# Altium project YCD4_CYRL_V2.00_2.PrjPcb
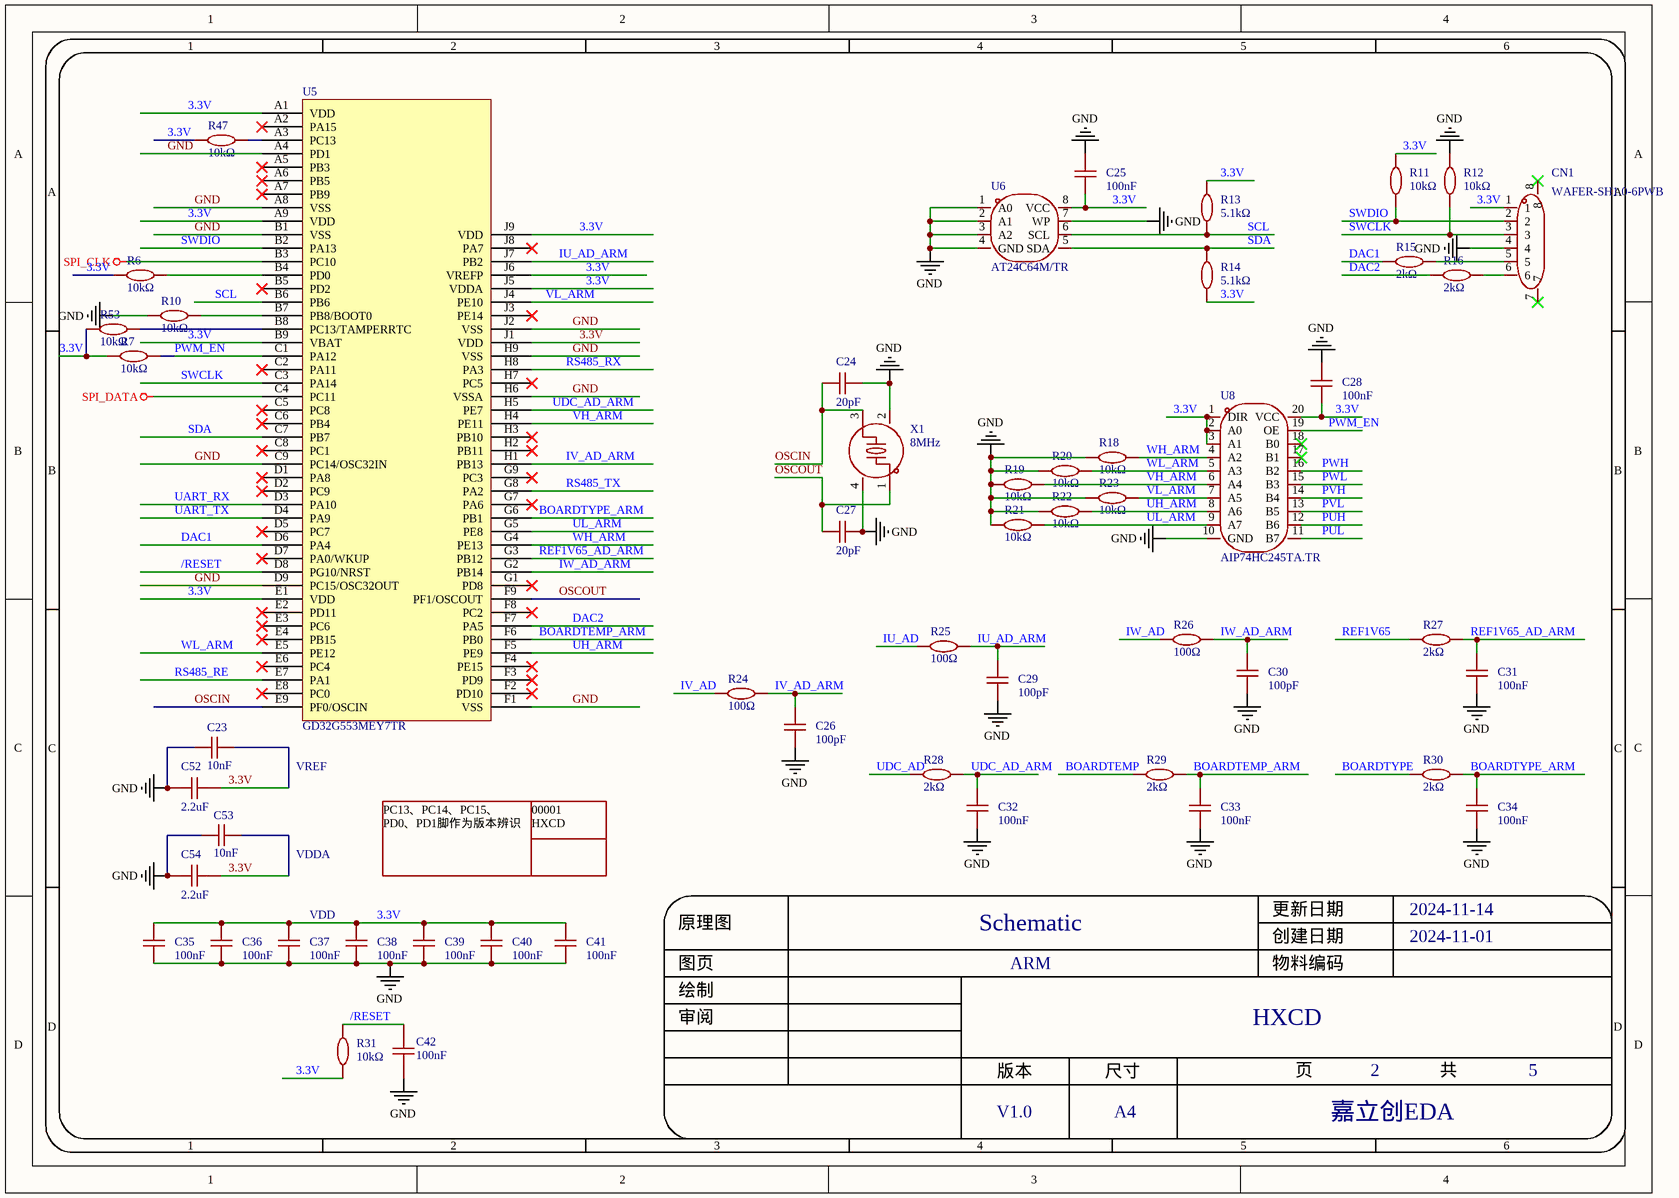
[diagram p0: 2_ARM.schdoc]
5 sheets, 208 parts. Net scope: global (net labels, ports and power ports of the same name join across sheets).
Board file: YCD4_CYRL_V2.00_2.PcbDoc
Sheets:
  2_ARM.schdoc
  5_DRIVE.schdoc
  3_COM.schdoc
  4_SAMP.schdoc
  1_POWER.schdoc

## Sheet 2_ARM.schdoc
size 309 x 223 mm; Symbol: Sheet-Symbol_A4; Device: Sheet-Symbol_A4; Company: 嘉立创EDA; Version: V1.0; Page Size: A4; @Project Name: HXCD; @Page Count: 5; @Update Date: 2024-11-14; @Create Date: 2024-11-01; @Schematic Name: Schematic; @Page No: 2; @Page Name: ARM; @Board Name: Board1; @Create Time: 20:30:37; @Update Time: 22:14:38; SheetNumber: 1; SheetTotal: 5

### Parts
C23  10nF  [C0402]
C24  20pF  [C0402]
C25  100nF  [C0402]
C26  100pF  [C0402]
C27  20pF  [C0402]
C28  100nF  [C0402]
C29  100pF  [C0402]
C30  100pF  [C0402]
C31  100nF  [C0402]
C32  100nF  [C0402]
C33  100nF  [C0402]
C34  100nF  [C0402]
C35  100nF  [C0402]
C36  100nF  [C0402]
C37  100nF  [C0402]
C38  100nF  [C0402]
C39  100nF  [C0402]
C40  100nF  [C0402]
C41  100nF  [C0402]
C42  100nF  [C0402]
C52  2.2uF  [C0402]
C53  10nF  [C0402]
C54  2.2uF  [C0402]
CN1  WAFER-SH1.0-6PWB  [CONN-SMD_6P-P1.00_XUNPU_WAFER-SH1.0-6PWB]
R6  10kΩ  [R0402]
R7  10kΩ  [R0402]
R10  10kΩ  [R0402]
R11  10kΩ  [R0402]
R12  10kΩ  [R0402]
R13  5.1kΩ  [R0402]
R14  5.1kΩ  [R0402]
R15  2kΩ  [R0402]
R16  2kΩ  [R0402]
R18  10kΩ  [R0402]
R19  10kΩ  [R0402]
R20  10kΩ  [R0402]
R21  10kΩ  [R0402]
R22  10kΩ  [R0402]
R23  10kΩ  [R0402]
R24  100Ω  [R0402]
R25  100Ω  [R0402]
R26  100Ω  [R0402]
R27  2kΩ  [R0402]
R28  2kΩ  [R0402]
R29  2kΩ  [R0402]
R30  2kΩ  [R0402]
R31  10kΩ  [R0402]
R47  10kΩ  [R0402]
R53  10kΩ  [R0402]
U5  GD32G553MEY7TR  [GD32G553MEY7TR]
U6  AT24C64M/TR  [SOP-8_L4.9-W3.9-P1.27-LS6.0-BL]
U8  AIP74HC245TA.TR  [TSSOP-20_L6.5-W4.4-P0.65-LS6.4-BL]
X1  8MHz  [CRYSTAL-SMD_4P-L3.2-W2.5-BL]

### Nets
3.3V: C23.2 C25.2 C28.2 C35.1 C36.1 C37.1 C38.1 C39.1 C40.1 C41.1 C52.1 C53.2 C54.1 CN1.1 R6.2 R7.2 R11.1 R13.2 R14.1 R31.2 R47.2 R53.2 U5.A1(VDD) U5.A9(VDD) U5.B9(VBAT) U5.E1(VDD) U5.J1(VDD) U5.J5(VDDA) U5.J6(VREFP) U5.J9(VDD) U6.8(VCC) U8.1(DIR) U8.2(A0) U8.3(A1) U8.20(VCC)
GND: C23.1 C24.2 C25.1 C26.1 C27.2 C28.1 C29.1 C30.1 C31.2 C32.2 C33.2 C34.2 C35.2 C36.2 C37.2 C38.2 C39.2 C40.2 C41.2 C42.1 C52.2 C53.1 C54.2 CN1.4 R10.2 R12.1 R18.2 R19.2 R20.2 R21.2 R22.2 R23.2 U5.A4(PD1) U5.A8(VSS) U5.B1(VSS) U5.C9(PC14/OSC32IN) U5.D9(PC15/OSC32OUT) U5.F1(VSS) U5.H6(VSSA) U5.H9(VSS) U5.J2(VSS) U6.1(A0) U6.2(A1) U6.3(A2) U6.4(GND) U6.7(WP) U8.10(GND) X1.2(GND) X1.4(GND)
SPI_CLK: U5.B3(PC10)
SPI_DATA: U5.C4(PC11)
/RESET: C42.2 R31.1 U5.D8(PG10/NRST)
BOARDTEMP: R29.1
BOARDTEMP_ARM: C33.1 R29.2 U5.F6(PB0)
BOARDTYPE: R30.1
BOARDTYPE_ARM: C34.1 R30.2 U5.G6(PB1)
DAC1: R15.1 U5.D6(PA4)
DAC2: R16.1 U5.F7(PA5)
IU_AD: R25.1
IU_AD_ARM: C29.2 R25.2 U5.J7(PB2)
IV_AD: R24.1
IV_AD_ARM: C26.2 R24.2 U5.H1(PB13)
IW_AD: R26.1
IW_AD_ARM: C30.2 R26.2 U5.G2(PB14)
OSCIN: C24.1 U5.E9(PF0/OSCIN) X1.3
OSCOUT: C27.1 U5.F9(PF1/OSCOUT) X1.1
PUH: U8.12(B6)
PUL: U8.11(B7)
PVH: U8.14(B4)
PVL: U8.13(B5)
PWH: U8.16(B2)
PWL: U8.15(B3)
PWM_EN: R7.1 U5.C1(PA12) U8.19(OE)
REF1V65: R27.1
REF1V65_AD_ARM: C31.1 R27.2 U5.G3(PB12)
RS485_RE: U5.E7(PA1)
RS485_RX: U5.H8(PA3)
RS485_TX: U5.G8(PA2)
SCL: R13.1 U5.B6(PB6) U6.6(SCL)
SDA: R14.2 U5.C7(PB7) U6.5(SDA)
SWCLK: CN1.3 R12.2 U5.C3(PA14)
SWDIO: CN1.2 R11.2 U5.B2(PA13)
UART_RX: U5.D3(PA10)
UART_TX: U5.D4(PA9)
UDC_AD: R28.1
UDC_AD_ARM: C32.1 R28.2 U5.H5(PE7)
UH_ARM: R22.1 U5.F5(PE9) U8.8(A6)
UL_ARM: R21.1 U5.G5(PE8) U8.9(A7)
VH_ARM: R19.1 U5.H4(PE11) U8.6(A4)
VL_ARM: R23.1 U5.J4(PE10) U8.7(A5)
WH_ARM: R18.1 U5.G4(PE13) U8.4(A2)
WL_ARM: R20.1 U5.E5(PE12) U8.5(A3)
NetCN1_5: CN1.5 R15.2
NetCN1_6: CN1.6 R16.2
NetR6_1: R6.1 U5.B4(PD0)
NetR10_1: R10.1 U5.B7(PB8/BOOT0)
NetR47_1: R47.1 U5.A3(PC13)
NetR53_1: R53.1 U5.B8(PC13/TAMPERRTC)

Not connected (* = marked no-connect by the designer): CN1 7* 8*; U5 A2(PA15)* A5(PB3)* A6(PB5)* A7(PB9)* B5(PD2)* C2(PA11)* C5(PC8)* C6(PB4)* C8(PC1)* D1(PA8)* D2(PC9)* D5(PC7)* D7(PA0/WKUP)* E2(PD11)* E3(PC6)* E4(PB15)* E6(PC4)* E8(PC0)* F2(PD10)* F3(PD9)* F4(PE15)* F8(PC2)* G1(PD8)* G7(PA6)* G9(PC3)* H2(PB11)* H3(PB10)* H7(PC5)* J3(PE14)* J8(PA7)*; U8 17(B1)* 18(B0)*

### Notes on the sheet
- VREF
- VDDA
- PC13、PC14、PC15、
  PD0、PD1脚作为版本辨识
- 00001
  HXCD
- VDD

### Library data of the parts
C23 C53 = CC0402KRX7R9BB104: 容值:100nF;精度:±10%;额定电压:50V;材质(温度系数):X7R;; Manufacturer: YAGEO(国巨); Add into BOM: yes; Value: 100nF; Tolerance: ±10%; Voltage Rated: 50V; Temperature Coefficient: X7R
C24 C27 = 0402CG200J500NT: 容值:20pF;精度:±5%;额定电压:50V;材质(温度系数):C0G;; Manufacturer: FH(风华); Add into BOM: yes; Tolerance: ±5%; Voltage Rated: 50V; Temperature Coefficient: C0G
C25 C28 C31-C41 = CC0402KRX7R9BB104: 容值:100nF;精度:±10%;额定电压:50V;材质(温度系数):X7R;; Manufacturer: YAGEO(国巨); Add into BOM: yes; Tolerance: ±10%; Voltage Rated: 50V; Temperature Coefficient: X7R
C26 C29 C30 = 0402CG101J500NT: 容值:100pF;精度:±5%;额定电压:50V;材质(温度系数):C0G;; Manufacturer: FH(风华); Add into BOM: yes; Tolerance: ±5%; Voltage Rated: 50V; Temperature Coefficient: C0G
C42 = CC0402KRX7R9BB104: 容值:100nF;精度:±10%;额定电压:50V;材质(温度系数):X7R;; Manufacturer: YAGEO(国巨); Symbol: CC0603KRX7R0BB104; Add into BOM: yes; Tolerance: ±10%; Voltage Rated: 50V; Temperature Coefficient: X7R
C52 C54 = CC0402KRX5R6BB225: 容值:2.2uF;精度:±10%;额定电压:10V;材质(温度系数):X5R;; Manufacturer: YAGEO(国巨); Add into BOM: yes; Tolerance: ±10%; Voltage Rated: 10V; Temperature Coefficient: X5R
CN1 = WAFER-SH1.0-6PWB: 插针结构:1x6P;间距:1mm;安装方式:卧贴;总PIN数:6P;排数:1;每排PIN数:6;额定电流:1A;工作温度范围:-25℃~+85℃;; Manufacturer: XUNPU(讯普); Add into BOM: yes; Pins Structure: 1x6P; Pitch: 1mm; Number of PINs Per Row: 6; Current Rating (Max): 1A
R6 R7 R10-R12 R31 R47 R53 = 0402WGF1002TCE: 电阻类型:厚膜电阻;阻值:10kΩ;精度:±1%;功率:62.5mW;最大工作电压:50V;温度系数:±100ppm/℃;; Manufacturer: UNI-ROYAL(厚声); Add into BOM: yes; Tolerance: ±1%; Power(Watts): 62.5mW; Overload Voltage (Max): 50V
R13 R14 = 0402WGF5101TCE: 电阻类型:厚膜电阻;阻值:5.1kΩ;精度:±1%;功率:62.5mW;最大工作电压:50V;温度系数:±100ppm/℃;; Manufacturer: UNI-ROYAL(厚声); Symbol: 0603WAF5101T5E; Add into BOM: yes; Tolerance: ±1%; Power(Watts): 62.5mW; Overload Voltage (Max): 50V
R15 R16 R27-R30 = 0402WGF2001TCE: 电阻类型:厚膜电阻;阻值:2kΩ;精度:±1%;功率:62.5mW;最大工作电压:50V;温度系数:±100ppm/℃;; Manufacturer: UNI-ROYAL(厚声); Symbol: 0603WAF2001T5E; Add into BOM: yes; Tolerance: ±1%; Power(Watts): 62.5mW; Overload Voltage (Max): 50V
R18-R23 = 0402WGF1002TCE: 电阻类型:厚膜电阻;阻值:10kΩ;精度:±1%;功率:62.5mW;最大工作电压:50V;温度系数:±100ppm/℃;; Manufacturer: UNI-ROYAL(厚声); Symbol: RT0603BRE0710KL; Add into BOM: yes; Tolerance: ±1%; Power(Watts): 62.5mW; Overload Voltage (Max): 50V
R24-R26 = 0402WGF2001TCE: 电阻类型:厚膜电阻;阻值:2kΩ;精度:±1%;功率:62.5mW;最大工作电压:50V;温度系数:±100ppm/℃;; Manufacturer: UNI-ROYAL(厚声); Symbol: 0603WAF2001T5E; Add into BOM: yes; Value: 2kΩ; Tolerance: ±1%; Power(Watts): 62.5mW; Overload Voltage (Max): 50V
U6 = AT24C64M/TR: Manufacturer: HGSEMI(华冠); Add into BOM: yes
U8 = AIP74HC245TA.TR: 输入类型:-;电源电压:2V~6V;灌电流(IOL):7.8mA;拉电流(IOH):7.8mA;; Manufacturer: I-CORE(中微爱芯); Add into BOM: yes; output type: 三态; Supply Voltage: 2V~6V; Sink Current: 7.8mA
X1 = X32258MSB4SI: 晶振类型:贴片晶振;频率:8MHz;常温频差:±10ppm;外接负载电容:20pF;频率稳定度(全温):±20ppm;; Manufacturer: YXC(扬兴晶振); Add into BOM: yes; Crystal Type: 贴片晶振; Normal temperature Frequency Tolerance: ±10ppm; External load capacitor: 20pF; Frequency Stability(Full temperature range): ±20ppm

## Sheet 5_DRIVE.schdoc
size 309 x 223 mm; Symbol: Sheet-Symbol_A4; Device: Sheet-Symbol_A4; Company: 嘉立创EDA; Version: V1.0; Page Size: A4; @Project Name: HXCD; @Page Count: 5; @Update Date: 2024-11-15; @Create Date: 2024-11-06; @Schematic Name: Schematic; @Page No: 5; @Page Name: DRIVE; @Board Name: Board1; @Create Time: 09:37:48; @Update Time: 20:32:39; SheetNumber: 2; SheetTotal: 5
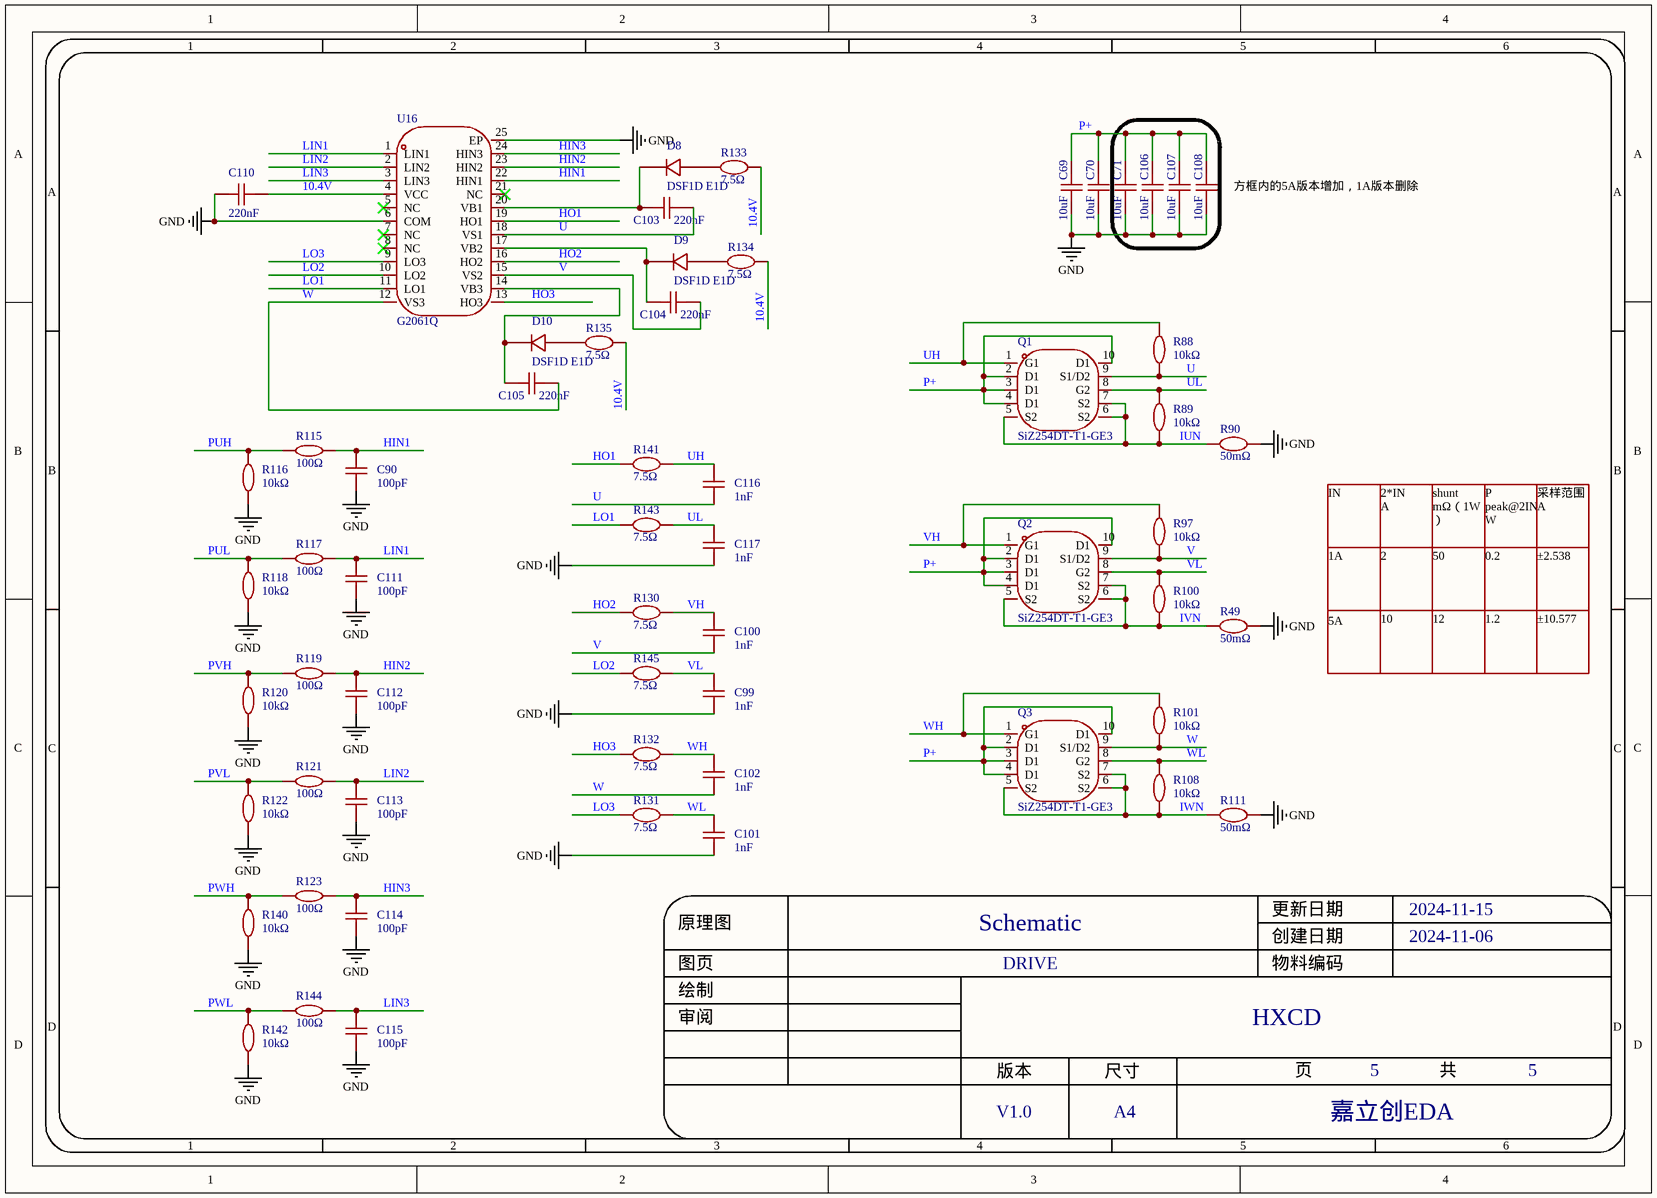
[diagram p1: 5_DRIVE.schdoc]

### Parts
C69  10uF  [C1210]
C70  10uF  [C1210]
C71  10uF  [C1210]
C90  100pF  [C0402]
C99  1nF  [C0402]
C100  1nF  [C0402]
C101  1nF  [C0402]
C102  1nF  [C0402]
C103  220nF  [C0402]
C104  220nF  [C0402]
C105  220nF  [C0402]
C106  10uF  [C1210]
C107  10uF  [C1210]
C108  10uF  [C1210]
C110  220nF  [C0402]
C111  100pF  [C0402]
C112  100pF  [C0402]
C113  100pF  [C0402]
C114  100pF  [C0402]
C115  100pF  [C0402]
C116  1nF  [C0402]
C117  1nF  [C0402]
D8  DSF1D E1D  [SOD-123_L2.8-W1.8-LS3.7-RD]
D9  DSF1D E1D  [SOD-123_L2.8-W1.8-LS3.7-RD]
D10  DSF1D E1D  [SOD-123_L2.8-W1.8-LS3.7-RD]
Q1  SiZ254DT-T1-GE3  [POWERPAIR-8_L3.3-W3.3-P0.65-BL_SIZ260DT-T1-GE3]
Q2  SiZ254DT-T1-GE3  [POWERPAIR-8_L3.3-W3.3-P0.65-BL_SIZ260DT-T1-GE3]
Q3  SiZ254DT-T1-GE3  [POWERPAIR-8_L3.3-W3.3-P0.65-BL_SIZ260DT-T1-GE3]
R49  50mΩ  [1206R]
R88  10kΩ  [R0402]
R89  10kΩ  [R0402]
R90  50mΩ  [R1206]
R97  10kΩ  [R0402]
R100  10kΩ  [R0402]
R101  10kΩ  [R0402]
R108  10kΩ  [R0402]
R111  50mΩ  [R1206]
R115  100Ω  [R0402]
R116  10kΩ  [R0402]
R117  100Ω  [R0402]
R118  10kΩ  [R0402]
R119  100Ω  [R0402]
R120  10kΩ  [R0402]
R121  100Ω  [R0402]
R122  10kΩ  [R0402]
R123  100Ω  [R0402]
R130  7.5Ω  [R0603]
R131  7.5Ω  [R0603]
R132  7.5Ω  [R0603]
R133  7.5Ω  [R0603]
R134  7.5Ω  [R0603]
R135  7.5Ω  [R0603]
R140  10kΩ  [R0402]
R141  7.5Ω  [R0603]
R142  10kΩ  [R0402]
R143  7.5Ω  [R0603]
R144  100Ω  [R0402]
R145  7.5Ω  [R0603]
U16  G2061Q  [QFN-24_L4.0-W4.0-P0.50-TL-EP2.7]

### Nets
10.4V: C110.2 R133.2 R134.2 R135.2 U16.4(VCC)
GND: C69.2 C70.2 C71.2 C90.1 C99.1 C101.1 C106.2 C107.2 C108.2 C110.1 C111.1 C112.1 C113.1 C114.1 C115.1 C117.1 R49.1 R90.1 R111.1 R116.1 R118.1 R120.1 R122.1 R140.1 R142.1 U16.6(COM) U16.25(EP)
HIN1: C90.2 R115.2 U16.22(HIN1)
HIN2: C112.2 R119.2 U16.23(HIN2)
HIN3: C114.2 R123.2 U16.24(HIN3)
HO1: R141.1 U16.19(HO1)
HO2: R130.1 U16.16(HO2)
HO3: R132.1 U16.13(HO3)
IUN: Q1.5(S2) Q1.6(S2) Q1.7(S2) R89.1 R90.2
IVN: Q2.5(S2) Q2.6(S2) Q2.7(S2) R49.2 R100.1
IWN: Q3.5(S2) Q3.6(S2) Q3.7(S2) R108.1 R111.2
LIN1: C111.2 R117.2 U16.1(LIN1)
LIN2: C113.2 R121.2 U16.2(LIN2)
LIN3: C115.2 R144.2 U16.3(LIN3)
LO1: R143.1 U16.11(LO1)
LO2: R145.1 U16.10(LO2)
LO3: R131.1 U16.9(LO3)
P+: C69.1 C70.1 C71.1 C106.1 C107.1 C108.1 Q1.2(D1) Q1.3(D1) Q1.4(D1) Q1.10(D1) Q2.2(D1) Q2.3(D1) Q2.4(D1) Q2.10(D1) Q3.2(D1) Q3.3(D1) Q3.4(D1) Q3.10(D1)
PUH: R115.1 R116.2
PUL: R117.1 R118.2
PVH: R119.1 R120.2
PVL: R121.1 R122.2
PWH: R123.1 R140.2
PWL: R142.2 R144.1
U: C103.1 C116.1 Q1.9(S1/D2) R88.1 U16.18(VS1)
UH: C116.2 Q1.1(G1) R88.2 R141.2
UL: C117.2 Q1.8(G2) R89.2 R143.2
V: C100.1 C104.1 Q2.9(S1/D2) R97.1 U16.15(VS2)
VH: C100.2 Q2.1(G1) R97.2 R130.2
VL: C99.2 Q2.8(G2) R100.2 R145.2
W: C102.1 C105.1 Q3.9(S1/D2) R101.1 U16.12(VS3)
WH: C102.2 Q3.1(G1) R101.2 R132.2
WL: C101.2 Q3.8(G2) R108.2 R131.2
NetC103_2: C103.2 D8.1 U16.20(VB1)
NetC104_2: C104.2 D9.1 U16.17(VB2)
NetC105_2: C105.2 D10.1 U16.14(VB3)
NetD8_2: D8.2 R133.1
NetD9_2: D9.2 R134.1
NetD10_2: D10.2 R135.1

Not connected (* = marked no-connect by the designer): U16 5(NC)* 7(NC)* 8(NC)* 21(NC)*

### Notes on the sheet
- (near C108) 方框内的5A版本增加，1A版本删除
- IN
- 1A
- 2*IN
  A
- 2
- shunt
  mΩ（1W）
- 50
- P peak@2IN
  W
- 0.2
- 采样范围
  A
- ±2.538
- 5A
- 10
- 12
- 1.2
- ±10.577

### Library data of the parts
C69 C70 = C1210X7R106K101NT: 容值:10uF;额定电压:100V;温度系数:-;; Manufacturer: SANYEAR(叁叶源); Add into BOM: yes; Voltage Rated: 100V
C71 C106-C108 = C1210X7R106K101NT: 容值:10uF;额定电压:100V;温度系数:-;; Manufacturer: SANYEAR(叁叶源); Add into BOM: no; Voltage Rated: 100V
C90 C111-C115 = 0402CG101J500NT: as C26 on sheet 2_ARM
C99-C102 C116 C117 = CC0402KRX7R9BB102: 容值:1nF;精度:±10%;额定电压:50V;材质(温度系数):X7R;; Manufacturer: YAGEO(国巨); Add into BOM: yes; Tolerance: ±10%; Voltage Rated: 50V; Temperature Coefficient: X7R
C103-C105 C110 = GRM155R61H224KE01D: 容值:220nF;精度:±10%;额定电压:50V;材质(温度系数):X5R;; Manufacturer: muRata(村田); Add into BOM: yes; Tolerance: ±10%; Voltage Rated: 50V; Temperature Coefficient: X5R
D8-D10 = DSF1D E1D: 二极管配置:独立式;正向压降(Vf):1V@1A;直流反向耐压(Vr):200V;整流电流:1A;反向恢复时间(trr):35ns;; Manufacturer: MDD(辰达半导体); Add into BOM: yes; Diode Configuration: 独立式; Forward Voltage (Vf@If): 1V@1A; Reverse Voltage (Vr): 200V; Rectified Current: 1A; Reverse Leakage Current: 5uA@200V; Reverse Recovery Time (trr): 35ns
Q1-Q3 = SiZ254DT-T1-GE3: Manufacturer: VISHAY(威世); Add into BOM: yes
R49 R90 R111 = RLM12FTCMR050: 电阻类型:采样电阻;阻值:50mΩ;精度:±1%;额定压降:-;功率:1W;安装方式:贴片;; Manufacturer: 大毅科技; Add into BOM: yes; Tolerance: ±1%; Power(Watts): 1W; Mounting Sytle: 贴片
R88 R89 R97 R100 R101 R108 R116 R118 R120 R122 R140 R142 = 0402WGF1002TCE: as R6 on sheet 2_ARM
R115 R117 R119 R121 R123 R144 = 0402WGF1000TCE: 电阻类型:厚膜电阻;阻值:100Ω;精度:±1%;功率:62.5mW;最大工作电压:50V;温度系数:±200ppm/℃;; Manufacturer: UNI-ROYAL(厚声); Add into BOM: yes; Tolerance: ±1%; Power(Watts): 62.5mW; Overload Voltage (Max): 50V
R130-R135 R141 R143 R145 = FRC0603F7R50TS: 电阻类型:厚膜电阻;阻值:7.5Ω;精度:±1%;功率:100mW;最大工作电压:75V;温度系数:±200ppm/℃;; Manufacturer: FOJAN(富捷); Add into BOM: yes; Tolerance: ±1%; Power(Watts): 100mW; Overload Voltage (Max): 75V
U16 = G2061Q: 驱动通道数:6;峰值灌电流:1.8A;峰值拉电流:1.5A;电源电压:8V~20V;上升时间:30ns;下降时间:30ns;是否隔离:非隔离;; Manufacturer: WXNSIC(国硅集成); Add into BOM: yes; Number of Drivers: 6; Peak Output Current(sink): 1.8A; Peak Output Current(source): 1.5A; Supply Voltage: 8V~20V; Rise Time: 30ns; Whether the isolation: 非隔离

## Sheet 3_COM.schdoc
size 309 x 223 mm; Symbol: Sheet-Symbol_A4; Device: Sheet-Symbol_A4; Company: 嘉立创EDA; Version: V1.0; Page Size: A4; @Project Name: HXCD; @Page Count: 5; @Update Date: 2024-11-15; @Create Date: 2024-11-11; @Schematic Name: Schematic; @Page No: 3; @Page Name: COM; @Board Name: Board1; @Create Time: 17:13:37; @Update Time: 20:32:31; SheetNumber: 3; SheetTotal: 5
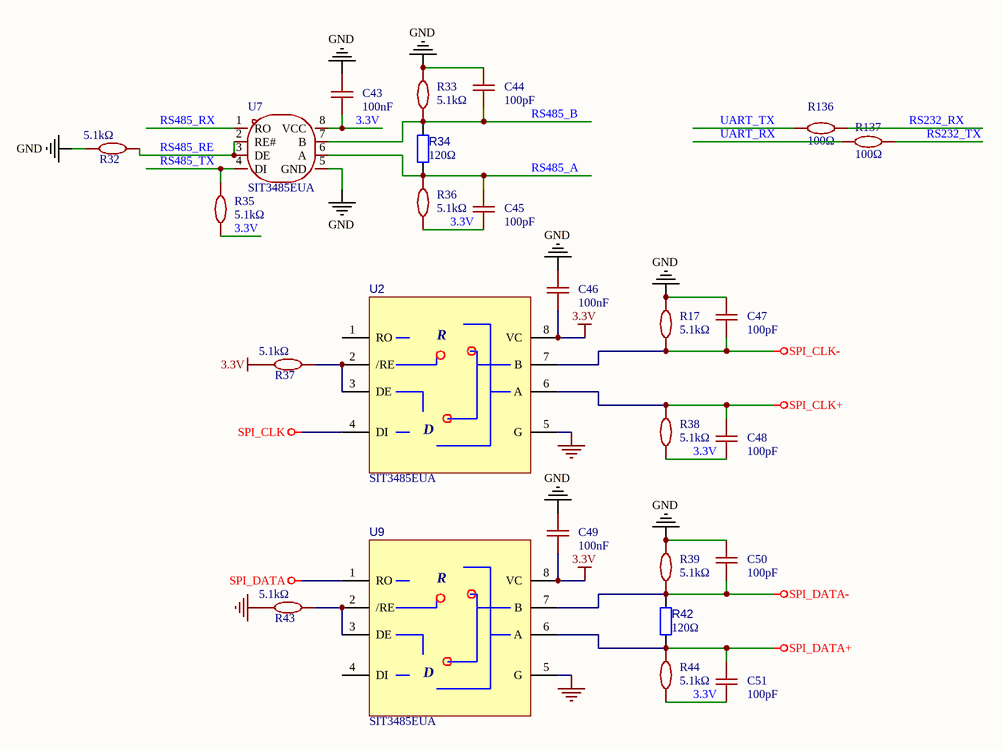
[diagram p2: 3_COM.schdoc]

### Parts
C43  100nF  [C0402]
C44  100pF  [C0402]
C45  100pF  [C0402]
C46  100nF  [C0402]
C47  100pF  [C0402]
C48  100pF  [C0402]
C49  100nF  [C0402]
C50  100pF  [C0402]
C51  100pF  [C0402]
R17  5.1kΩ  [R0402]
R32  5.1kΩ  [R0402]
R33  5.1kΩ  [R0402]
R34  120Ω  [R1206]
R35  5.1kΩ  [R0402]
R36  5.1kΩ  [R0402]
R37  5.1kΩ  [R0402]
R38  5.1kΩ  [R0402]
R39  5.1kΩ  [R0402]
R42  120Ω  [R1206]
R43  5.1kΩ  [R0402]
R44  5.1kΩ  [R0402]
R136  100Ω  [R0402]
R137  100Ω  [R0402]
U2  SIT3485EUA  [MSOP-8_L3.0-W3.0-P0.65-LS5.0-BL]
U7  SIT3485EUA  [MSOP-8_L3.0-W3.0-P0.65-LS5.0-BL]
U9  SIT3485EUA  [MSOP-8_L3.0-W3.0-P0.65-LS5.0-BL]

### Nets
3.3V: C43.2 C45.1 C46.2 C48.1 C49.2 C51.1 R35.1 R36.1 R37.2 R38.1 R44.1 U2.8(VC) U7.8(VCC) U9.8(VC)
GND: C43.1 C44.2 C46.1 C47.2 C49.1 C50.2 R17.2 R32.2 R33.2 R39.2 R43.2 U2.5(G) U7.5(GND) U9.5(G)
SPI_CLK: U2.4(DI)
SPI_CLK+: C48.2 R38.2 U2.6(A)
SPI_CLK-: C47.1 R17.1 U2.7(B)
SPI_DATA: U9.1(RO)
SPI_DATA+: C51.2 R42.1 R44.2 U9.6(A)
SPI_DATA-: C50.1 R39.1 R42.2 U9.7(B)
RS232_RX: R136.2
RS232_TX: R137.2
RS485_A: C45.2 R34.1 R36.2 U7.6(A)
RS485_B: C44.1 R33.1 R34.2 U7.7(B)
RS485_RE: R32.1 U7.2(RE#) U7.3(DE)
RS485_RX: U7.1(RO)
RS485_TX: R35.2 U7.4(DI)
UART_RX: R137.1
UART_TX: R136.1
NetR37_1: R37.1 U2.2(/RE) U2.3(DE)
NetR43_1: R43.1 U9.2(/RE) U9.3(DE)

Not connected (* = marked no-connect by the designer): U2 1(RO); U9 4(DI)

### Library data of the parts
C43 C46 C49 = CC0402KRX7R9BB104: as C25 on sheet 2_ARM
C44 C45 C47 C48 C50 C51 = 0402CG101J500NT: as C26 on sheet 2_ARM
R17 R32 R33 R35-R39 R43 R44 = 0402WGF5101TCE: as R13 on sheet 2_ARM
R34 R42 = Res2: Resistor
R136 R137 = 0402WGF2001TCE: as R24 on sheet 2_ARM
U7 = SIT3485EUA: 类型:收发器;数据速率:12Mbps;驱动器/接收器:1/1;; Manufacturer: SIT(芯力特); Add into BOM: yes; Types: 收发器; Supply Voltage: 3V~3.6V; Data Rate: 12Mbps; Driver/receiver: 1/1; Node Number: 256; Whether the isolation: 否

## Sheet 4_SAMP.schdoc
size 309 x 223 mm; Symbol: Sheet-Symbol_A4; Device: Sheet-Symbol_A4; Company: 嘉立创EDA; Version: V1.0; Page Size: A4; @Project Name: HXCD; @Page Count: 5; @Update Date: 2024-11-14; @Create Date: 2024-11-05; @Schematic Name: Schematic; @Page No: 4; @Page Name: SAMP; @Board Name: Board1; @Create Time: 11:39:32; @Update Time: 22:12:28; SheetNumber: 4; SheetTotal: 5
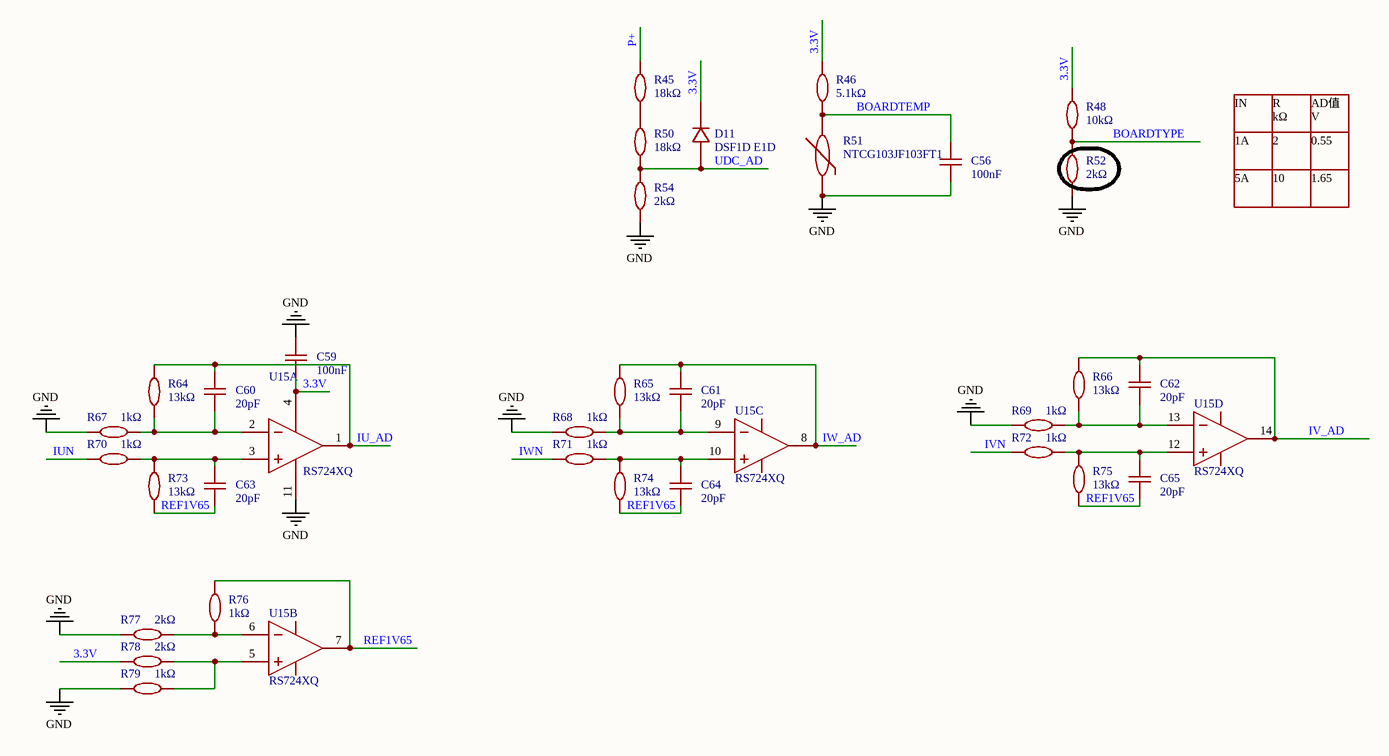
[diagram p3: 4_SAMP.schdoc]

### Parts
C56  100nF  [C0402]
C59  100nF  [C0402]
C60  20pF  [C0402]
C61  20pF  [C0402]
C62  20pF  [C0402]
C63  20pF  [C0402]
C64  20pF  [C0402]
C65  20pF  [C0402]
D11  DSF1D E1D  [SOD-123_L2.8-W1.8-LS3.7-RD]
R45  18kΩ  [R0603]
R46  5.1kΩ  [R0402]
R48  10kΩ  [R0402]
R50  18kΩ  [R0603]
R51  NTCG103JF103FT1  [R0402]
R52  2kΩ  [R0402]
R54  2kΩ  [R0603]
R64  13kΩ  [R0402]
R65  13kΩ  [R0402]
R66  13kΩ  [R0402]
R67  1kΩ  [R0402]
R68  1kΩ  [R0402]
R69  1kΩ  [R0402]
R70  1kΩ  [R0402]
R71  1kΩ  [R0402]
R72  1kΩ  [R0402]
R73  13kΩ  [R0402]
R74  13kΩ  [R0402]
R75  13kΩ  [R0402]
R76  1kΩ  [R0402]
R77  2kΩ  [R0402]
R78  2kΩ  [R0402]
R79  1kΩ  [R0402]
U15  RS724XQ  [TSSOP-14_L5.0-W4.4-P0.65-LS6.4-BL]  (parts A,B,C,D of 4)

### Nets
3.3V: C59.2 D11.1 R46.2 R48.1 R78.1 U15.4(V+)
GND: C56.2 C59.1 R51.1 R52.1 R54.1 R67.1 R68.1 R69.1 R77.1 R79.1 U15.11(V-)
BOARDTEMP: C56.1 R46.1 R51.2
BOARDTYPE: R48.2 R52.2
IU_AD: C60.2 R64.2 U15.1(OUTA)
IUN: R70.1
IV_AD: C62.2 R66.2 U15.14(OUTD)
IVN: R72.1
IW_AD: C61.2 R65.2 U15.8(OUTC)
IWN: R71.1
P+: R45.2
REF1V65: C63.1 C64.1 C65.1 R73.1 R74.1 R75.1 R76.2 U15.7(OUTB)
UDC_AD: D11.2 R50.1 R54.2
NetC60_1: C60.1 R64.1 R67.2 U15.2(-INA)
NetC61_1: C61.1 R65.1 R68.2 U15.9(-INC)
NetC62_1: C62.1 R66.1 R69.2 U15.13(-IND)
NetC63_2: C63.2 R70.2 R73.2 U15.3(+INA)
NetC64_2: C64.2 R71.2 R74.2 U15.10(+INC)
NetC65_2: C65.2 R72.2 R75.2 U15.12(+IND)
NetR45_1: R45.1 R50.2
NetR76_1: R76.1 R77.2 U15.6(-INB)
NetR78_2: R78.2 R79.2 U15.5(+INB)

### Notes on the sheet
- IN
- 1A
- 5A
- R
  kΩ
- 2
- 10
- AD值
  V
- 0.55
- 1.65

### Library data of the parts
C56 C59 = CC0402KRX7R9BB104: as C25 on sheet 2_ARM
C60-C65 = 0402CG200J500NT: as C24 on sheet 2_ARM
D11 = DSF1D E1D: as D8 on sheet 5_DRIVE
R45 R50 = 0603WAF1802T5E: 电阻类型:厚膜电阻;阻值:18kΩ;精度:±1%;功率:100mW;最大工作电压:75V;温度系数:±100ppm/℃;; Manufacturer: UNI-ROYAL(厚声); Add into BOM: yes; Tolerance: ±1%; Power(Watts): 100mW; Overload Voltage (Max): 75V
R46 = 0402WGF5101TCE: as R13 on sheet 2_ARM
R48 = 0402WGF1002TCE: as R6 on sheet 2_ARM
R51 = NTCG103JF103FT1: 阻值(25℃):10kΩ;B值(25℃/50℃):3380K;电阻精度:±1%;功率:100mW;B值精度:±1%;最大稳态电流(25℃):310uA;; Manufacturer: TDK; Add into BOM: yes; Resistance @ 25℃: 10kΩ; B Constant (25℃/50℃): 3380K; Resistance Tolerance: ±1%; B Constant (25℃/75℃): 3422K; B Constant (25℃/85℃): 3435K; B Constant (25℃/100℃): 3453K; Power: 100mW; Steady State Current (Max): 310uA
R52 R77 R78 = 0402WGF2001TCE: as R15 on sheet 2_ARM
R54 = 0603WAF2001T5E: 电阻类型:厚膜电阻;阻值:2kΩ;精度:±1%;功率:100mW;最大工作电压:75V;温度系数:±100ppm/℃;; Manufacturer: UNI-ROYAL(厚声); Add into BOM: yes; Tolerance: ±1%; Power(Watts): 100mW; Overload Voltage (Max): 75V
R64-R66 R73-R75 = 0402WGF1302TCE: 电阻类型:厚膜电阻;阻值:13kΩ;精度:±1%;功率:62.5mW;最大工作电压:50V;温度系数:±100ppm/℃;; Manufacturer: UNI-ROYAL(厚声); Add into BOM: yes; Tolerance: ±1%; Power(Watts): 62.5mW; Overload Voltage (Max): 50V
R67-R72 R76 R79 = 0402WGF1001TCE: 电阻类型:厚膜电阻;阻值:1kΩ;精度:±1%;功率:62.5mW;最大工作电压:50V;温度系数:±100ppm/℃;; Manufacturer: UNI-ROYAL(厚声); Add into BOM: yes; Tolerance: ±1%; Power(Watts): 62.5mW; Overload Voltage (Max): 50V
U15 = RS724XQ: 放大器数:四路;增益带宽积(GBP):10MHz;输入偏置电流(Ib):1pA;压摆率(SR):7V/us;带宽(-3db):-;轨到轨:-;; Manufacturer: RUNIC(润石); Add into BOM: yes; Number of Circuits: 四路; Gain Bandwidth Product(GBP): 10MHz; Current - Input Bias(Ib): 1pA; Slew Rate(SR): 7V/us; Output Current: 70mA; Relevance: []

## Sheet 1_POWER.schdoc
size 309 x 223 mm; Symbol: Sheet-Symbol_A4; Device: Sheet-Symbol_A4; Company: 嘉立创EDA; Version: V1.0; Page Size: A4; @Project Name: HXCD; @Page Count: 5; @Update Date: 2024-11-15; @Create Date: 2024-11-01; @Schematic Name: Schematic; @Page No: 1; @Page Name: POWER; @Board Name: Board1; @Create Time: 19:48:33; @Update Time: 23:02:23; SheetNumber: 5; SheetTotal: 5
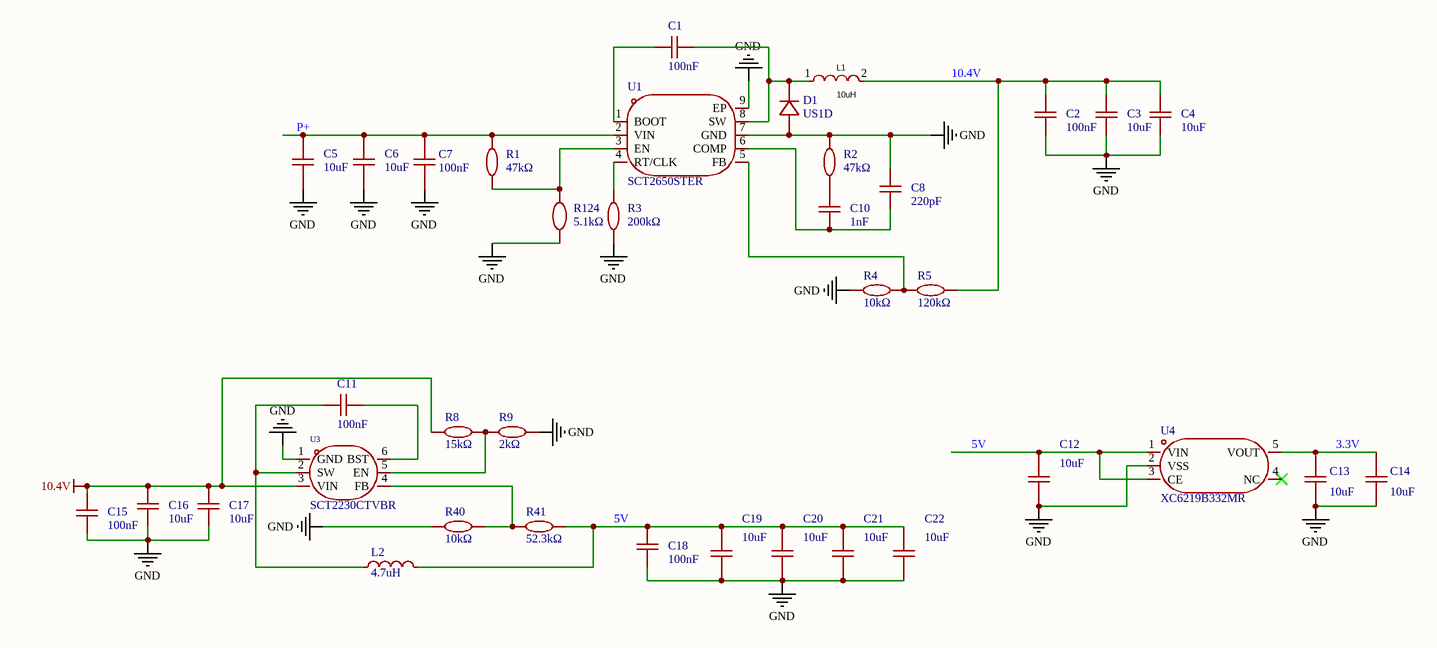
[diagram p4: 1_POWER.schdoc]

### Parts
C1  100nF  [C0402]
C2  100nF  [C0402]
C3  10uF  [C0805]
C4  10uF  [C0805]
C5  10uF  [C1210]
C6  10uF  [C1210]
C7  100nF  [C0603]
C8  220pF  [C0402]
C10  1nF  [C0402]
C11  100nF  [C0402]
C12  10uF  [C0603]
C13  10uF  [C0603]
C14  10uF  [C0603]
C15  100nF  [C0402]
C16  10uF  [C0805]
C17  10uF  [C0805]
C18  100nF  [C0402]
C19  10uF  [C0603]
C20  10uF  [C0603]
C21  10uF  [C0603]
C22  10uF  [C0603]
D1  US1D  [SMA_L4.3-W2.6-LS5.1-RD]
L1  10uH  [IND-SMD_L4.0-W4.0]
L2  4.7uH  [IND-SMD_L2.5-W2.1]
R1  47kΩ  [R0402]
R2  47kΩ  [R0402]
R3  200kΩ  [R0402]
R4  10kΩ  [R0402]
R5  120kΩ  [R0402]
R8  15kΩ  [R0402]
R9  2kΩ  [R0402]
R40  10kΩ  [R0402]
R41  52.3kΩ  [R0402]
R124  5.1kΩ  [R0402]
U1  SCT2650STER  [ESOP-8_L4.9-W3.9-P1.27-LS6.0-BL-EP-2]
U3  SCT2230CTVBR  [TSOT-23-6_L2.9-W1.6-P0.95-LS2.8-BL]
U4  XC6219B332MR  [SOT-23-5_L3.0-W1.7-P0.95-LS2.8-BR]

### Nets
3.3V: C13.2 C14.2 U4.5(VOUT)
10.4V: C2.1 C3.1 C4.1 C15.1 C16.1 C17.1 L1.2 R5.2 R8.2 U3.3(VIN)
GND: C2.2 C3.2 C4.2 C5.2 C6.2 C7.1 C8.2 C12.1 C13.1 C14.1 C15.2 C16.2 C17.2 C18.2 C19.1 C20.1 C21.1 C22.1 D1.2(A) R2.2 R3.1 R4.2 R9.2 R40.2 R124.1 U1.7(GND) U1.9(EP) U3.1(GND) U4.2(VSS)
5V: C12.2 C18.1 C19.2 C20.2 C21.2 C22.2 L2.2 R41.2 U4.1(VIN) U4.3(CE)
P+: C5.1 C6.1 C7.2 R1.2 U1.2(VIN)
NetC1_1: C1.1 D1.1(K) L1.1 U1.8(SW)
NetC1_2: C1.2 U1.1(BOOT)
NetC8_1: C8.1 C10.1 U1.6(COMP)
NetC10_2: C10.2 R2.1
NetC11_1: C11.1 U3.6(BST)
NetC11_2: C11.2 L2.1 U3.2(SW)
NetR1_1: R1.1 R124.2 U1.3(EN)
NetR3_2: R3.2 U1.4(RT/CLK)
NetR4_1: R4.1 R5.1 U1.5(FB)
NetR8_1: R8.1 R9.1 U3.5(EN)
NetR40_1: R40.1 R41.1 U3.4(FB)

Not connected (* = marked no-connect by the designer): U4 4(NC)*

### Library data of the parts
C1 C2 C11 C15 C18 = CC0402KRX7R9BB104: as C25 on sheet 2_ARM
C3 C4 C16 C17 = 0805X106K250NT: 容值:10uF;精度:±10%;额定电压:25V;材质(温度系数):X5R;; Manufacturer: FH(风华); Add into BOM: yes; Tolerance: ±10%; Voltage Rated: 25V; Temperature Coefficient: X5R
C5 C6 = C1210X7R106K101NT: as C69 on sheet 5_DRIVE
C7 = CC0603KRX7R0BB104: 容值:100nF;精度:±10%;额定电压:100V;材质(温度系数):X7R;; Manufacturer: YAGEO(国巨); Add into BOM: yes; Tolerance: ±10%; Voltage Rated: 100V; Temperature Coefficient: X7R
C8 = CC0402KRX7R9BB221: 容值:220pF;精度:±10%;额定电压:50V;材质(温度系数):X7R;; Manufacturer: YAGEO(国巨); Add into BOM: yes; Tolerance: ±10%; Voltage Rated: 50V; Temperature Coefficient: X7R
C10 = CC0402KRX7R9BB102: as C99 on sheet 5_DRIVE
C12-C14 C19-C22 = CC0603KRX5R6BB106: 容值:10uF;精度:±10%;额定电压:10V;材质(温度系数):X5R;; Manufacturer: YAGEO(国巨); Add into BOM: yes; Tolerance: ±10%; Voltage Rated: 10V; Temperature Coefficient: X5R
D1 = US1D_C2848672: 二极管配置:独立式;正向压降(Vf):1V@1A;直流反向耐压(Vr):200V;平均整流电流(Io):1A;反向恢复时间(trr):75ns;; Manufacturer: GOODWORK(固得沃克); Add into BOM: yes; Diode Configuration: 独立式; Forward Voltage (Vf@If): 1V@1A; Reverse Voltage (Vr): 200V; Average Rectified Current (Io): 1A; Reverse Leakage Current: 5uA@200V; Reverse Recovery Time (trr): 75ns
L1 = PRS4018-100MT: Manufacturer: FH(风华); Add into BOM: yes; Tolerance: ±20%; Rated Current: 840mA; DC Resistance (DCR): 234mΩ
L2 = PRS2512-4R7MT: 电感值:4.7uH;精度:±20%;额定电流:840mA;; Manufacturer: FH(风华); Add into BOM: yes; Tolerance: ±20%; Rated Current: 840mA; DC Resistance (DCR): 273mΩ
R1 R8 = 0402WGF2003TCE: 电阻类型:厚膜电阻;阻值:200kΩ;精度:±1%;功率:62.5mW;最大工作电压:50V;温度系数:±100ppm/℃;; Manufacturer: UNI-ROYAL(厚声); Add into BOM: yes; Value: 200kΩ; Tolerance: ±1%; Power(Watts): 62.5mW; Overload Voltage (Max): 50V
R2 = 0402WGF4702TCE: 电阻类型:厚膜电阻;阻值:47kΩ;精度:±1%;功率:62.5mW;最大工作电压:50V;温度系数:±100ppm/℃;; Manufacturer: UNI-ROYAL(厚声); Add into BOM: yes; Tolerance: ±1%; Power(Watts): 62.5mW; Overload Voltage (Max): 50V
R3 = 0402WGF2003TCE: 电阻类型:厚膜电阻;阻值:200kΩ;精度:±1%;功率:62.5mW;最大工作电压:50V;温度系数:±100ppm/℃;; Manufacturer: UNI-ROYAL(厚声); Add into BOM: yes; Tolerance: ±1%; Power(Watts): 62.5mW; Overload Voltage (Max): 50V
R4 R40 = 0402WGF1002TCE: as R6 on sheet 2_ARM
R5 = 0402WGF1203TCE: 电阻类型:厚膜电阻;阻值:120kΩ;精度:±1%;功率:62.5mW;最大工作电压:50V;温度系数:±100ppm/℃;; Manufacturer: UNI-ROYAL(厚声); Add into BOM: yes; Tolerance: ±1%; Power(Watts): 62.5mW; Overload Voltage (Max): 50V
R9 = RC0402FR-0730KL: 电阻类型:厚膜电阻;阻值:30kΩ;精度:±1%;功率:62.5mW;最大工作电压:50V;温度系数:±100ppm/℃;; Manufacturer: YAGEO(国巨); Add into BOM: yes; Value: 30kΩ; Tolerance: ±1%; Power(Watts): 62.5mW; Overload Voltage (Max): 50V
R41 = 0402WGF5232TCE: 电阻类型:厚膜电阻;阻值:52.3kΩ;精度:±1%;功率:62.5mW;最大工作电压:50V;温度系数:±100ppm/℃;; Manufacturer: UNI-ROYAL(厚声); Add into BOM: yes; Tolerance: ±1%; Power(Watts): 62.5mW; Overload Voltage (Max): 50V
R124 = 0402WGF2502TCE: 电阻类型:厚膜电阻;阻值:25kΩ;精度:±1%;功率:62.5mW;最大工作电压:50V;温度系数:±100ppm/℃;; Manufacturer: UNI-ROYAL(厚声); Add into BOM: yes; Value: 25kΩ; Tolerance: ±1%; Power(Watts): 62.5mW; Overload Voltage (Max): 50V
U1 = SCT2650STER: 电源IC; Manufacturer: SCT(芯洲科技); Add into BOM: yes
U3 = SCT2230CTVBR: Manufacturer: SCT(芯洲科技); Add into BOM: yes
U4 = XC6219B332MR_C347386: 输出类型:固定;最大输入电压:7V;输出电压:3.3V;输出电流:300mA;电源纹波抑制比(PSRR):40dB@(1kHz);输出极性:正极;; Manufacturer: UMW(友台半导体); Add into BOM: yes; Output Type: 固定; Maximum Input Voltage: 7V; Output Voltage: 3.3V; Output Current: 300mA; Dropout Voltage: 280mV@(100mA); Output Polarity: 正极; Number of Outputs: 1

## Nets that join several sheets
3.3V: 2_ARM (35 pins), 3_COM (14 pins), 4_SAMP (6 pins), 1_POWER (C13.2 C14.2 U4.5)
10.4V: 5_DRIVE (5 pins), 1_POWER (10 pins)
GND: 2_ARM (49 pins), 5_DRIVE (27 pins), 3_COM (14 pins), 4_SAMP (11 pins), 1_POWER (29 pins)
SPI_CLK: 2_ARM (U5.B3), 3_COM (U2.4)
SPI_DATA: 2_ARM (U5.C4), 3_COM (U9.1)
BOARDTEMP: 2_ARM (R29.1), 4_SAMP (C56.1 R46.1 R51.2)
BOARDTYPE: 2_ARM (R30.1), 4_SAMP (R48.2 R52.2)
IU_AD: 2_ARM (R25.1), 4_SAMP (C60.2 R64.2 U15.1)
IUN: 5_DRIVE (5 pins), 4_SAMP (R70.1)
IV_AD: 2_ARM (R24.1), 4_SAMP (C62.2 R66.2 U15.14)
IVN: 5_DRIVE (5 pins), 4_SAMP (R72.1)
IW_AD: 2_ARM (R26.1), 4_SAMP (C61.2 R65.2 U15.8)
IWN: 5_DRIVE (5 pins), 4_SAMP (R71.1)
P+: 5_DRIVE (18 pins), 4_SAMP (R45.2), 1_POWER (5 pins)
PUH: 2_ARM (U8.12), 5_DRIVE (R115.1 R116.2)
PUL: 2_ARM (U8.11), 5_DRIVE (R117.1 R118.2)
PVH: 2_ARM (U8.14), 5_DRIVE (R119.1 R120.2)
PVL: 2_ARM (U8.13), 5_DRIVE (R121.1 R122.2)
PWH: 2_ARM (U8.16), 5_DRIVE (R123.1 R140.2)
PWL: 2_ARM (U8.15), 5_DRIVE (R142.2 R144.1)
REF1V65: 2_ARM (R27.1), 4_SAMP (8 pins)
RS485_RE: 2_ARM (U5.E7), 3_COM (R32.1 U7.2 U7.3)
RS485_RX: 2_ARM (U5.H8), 3_COM (U7.1)
RS485_TX: 2_ARM (U5.G8), 3_COM (R35.2 U7.4)
UART_RX: 2_ARM (U5.D3), 3_COM (R137.1)
UART_TX: 2_ARM (U5.D4), 3_COM (R136.1)
UDC_AD: 2_ARM (R28.1), 4_SAMP (D11.2 R50.1 R54.2)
